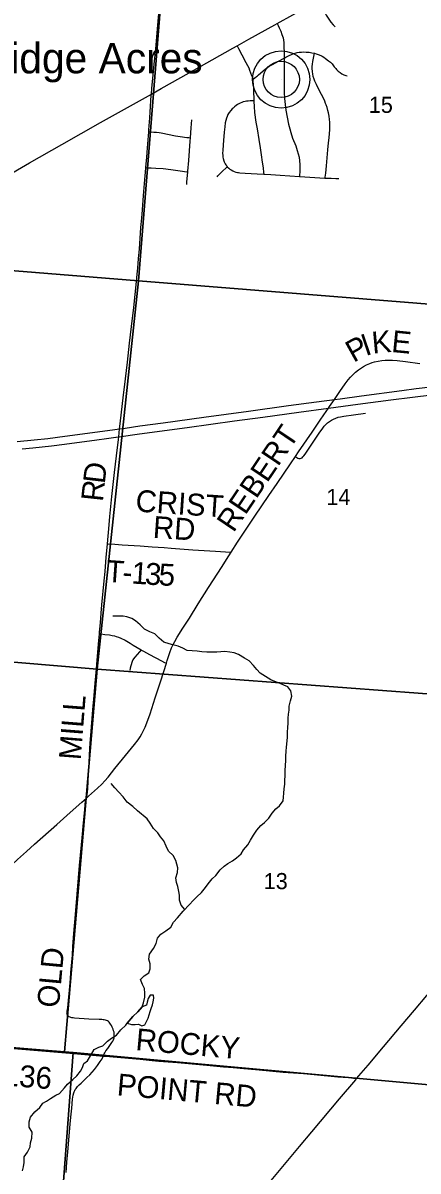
# Model space of a CAD drawing. Extents: x 0 to 1134, y 0 to 440.
# Drawn here: x 843.365 to 844.389, y 358.883 to 361.864 of the extents above; entities that cross this region are included whole.
import ezdxf

# ---------------------------------------------------------------- set-up
doc = ezdxf.new("R2010")
doc.units = 0
for name, color, linetype in [('GM_X_County_Road', 7, 'Continuous'), ('GM_X_County_Road_Text', 7, 'Continuous'), ('GM_X_Interstate_Route', 7, 'Continuous'), ('GM_X_Minor_Lake', 7, 'Continuous'), ('GM_X_Minor_River', 7, 'Continuous'), ('GM_X_Section', 7, 'Continuous'), ('GM_X_Section_Text', 7, 'Continuous'), ('GM_X_Township_Road', 7, 'Continuous'), ('GM_X_Township_Road_Text', 7, 'Continuous'), ('GM_X_Unincorporated', 7, 'Continuous'), ('GM_X_Unincorporated_Location', 7, 'Continuous'), ('GM_X_Unincorporated_Text', 7, 'Continuous')]:
    doc.layers.add(name, color=color, linetype=linetype)

msp = doc.modelspace()

# ---------------------------------------------------------------- linework, layer by layer
at = {"layer": 'GM_X_County_Road'}
for points in [[(844.0237, 361.8623), (844.0644, 361.8851), (844.1315, 361.9219)], [(843.92, 361.8044), (843.9506, 361.8216), (844.0174, 361.8588), (844.0237, 361.8623)], [(843.6977, 361.6793), (843.7229, 361.6933), (843.7743, 361.7225), (843.8556, 361.7681), (843.9091, 361.7983), (843.92, 361.8044)], [(843.3125, 361.4605), (843.3147, 361.4618), (843.382, 361.5007), (843.4655, 361.5487), (843.5657, 361.6051), (843.6822, 361.6707), (843.6977, 361.6793)], [(844.1449, 360.8463), (844.1568, 360.8637), (844.1598, 360.8682), (844.1722, 360.8863), (844.1861, 360.9066), (844.2003, 360.9271), (844.2079, 360.937), (844.214, 360.9441), (844.2205, 360.9508), (844.2273, 360.9572), (844.2345, 360.9633), (844.2396, 360.967), (844.2475, 360.972), (844.2558, 360.9763), (844.2644, 360.9801), (844.2703, 360.9822), (844.2763, 360.984), (844.2855, 360.9861), (844.2948, 360.9875), (844.3041, 360.9884), (844.3135, 360.9887), (844.3229, 360.9885), (844.3353, 360.9875), (844.3569, 360.9849), (844.3939, 360.98)], [(844.0711, 360.738), (844.0793, 360.75), (844.1144, 360.8013), (844.1353, 360.8322), (844.1449, 360.8463)], [(843.9046, 360.4899), (843.9212, 360.5156), (843.9366, 360.5389), (843.9519, 360.5623), (843.9657, 360.583), (844.0023, 360.6371), (844.0234, 360.6678), (844.0583, 360.7193), (844.0711, 360.738)], [(843.7366, 360.2016), (843.739, 360.209), (843.7458, 360.2297), (843.7501, 360.2414), (843.7539, 360.25), (843.7582, 360.2583), (843.7645, 360.2691), (843.7794, 360.2927), (843.7962, 360.3189), (843.8194, 360.3556), (843.8459, 360.3977), (843.8808, 360.4529), (843.8925, 360.4712), (843.9046, 360.4899)], [(843.5293, 359.851), (843.5347, 359.8559), (843.5578, 359.8767), (843.5689, 359.8875), (843.5773, 359.8965), (843.5853, 359.906), (843.6028, 359.9278), (843.6302, 359.9616), (843.6536, 359.9906), (843.663, 360.0029), (843.6683, 360.0106), (843.6731, 360.0185), (843.6774, 360.0267), (843.6813, 360.0351), (843.6859, 360.0466), (843.6941, 360.07), (843.7078, 360.1113), (843.7221, 360.1557), (843.7366, 360.2016)], [(842.9578, 359.3329), (842.9846, 359.3579), (843.0635, 359.4322), (843.0791, 359.4466), (843.1019, 359.4677), (843.1202, 359.4844), (843.1522, 359.5137), (843.1924, 359.5504), (843.2304, 359.5845), (843.2628, 359.6135), (843.2953, 359.6422), (843.3371, 359.6793), (843.3508, 359.6919), (843.3739, 359.7127), (843.3946, 359.7314), (843.4526, 359.783), (843.4874, 359.814), (843.5177, 359.8407), (843.5293, 359.851)], [(844.2299, 359.1229), (844.2596, 359.1582), (844.2997, 359.2057), (844.3457, 359.2604), (844.38, 359.3006), (844.4121, 359.3385), (844.4403, 359.3717), (844.4786, 359.4166), (844.4989, 359.4401), (844.5095, 359.4515), (844.5152, 359.4571)], [(843.9834, 358.8296), (844.0036, 358.8536), (844.0814, 358.9466), (844.1134, 358.9847), (844.1856, 359.0702), (844.2276, 359.1201), (844.2299, 359.1229)]]:
    msp.add_lwpolyline(points, dxfattribs=at)
at = {"layer": 'GM_X_Interstate_Route'}
msp.add_line((843.6051, 360.7882), (843.6061, 360.7883), dxfattribs=at)
for points in [[(843.6154, 360.8103), (843.6301, 360.8122), (843.6674, 360.8175), (843.7284, 360.8256), (843.8336, 360.84), (843.9498, 360.8562), (844.0536, 360.8703), (844.1259, 360.8802), (844.1722, 360.8863), (844.1871, 360.8883), (844.2427, 360.896), (844.3472, 360.91), (844.3842, 360.9147), (844.4521, 360.9222), (844.5148, 360.9288), (844.5746, 360.9344), (844.579, 360.9348)], [(843.6061, 360.7883), (843.6129, 360.7892), (843.6665, 360.7967), (843.7907, 360.8137), (843.9136, 360.8308), (843.9868, 360.8406), (844.0797, 360.8534), (844.1568, 360.8637), (844.2327, 360.8739), (844.3189, 360.8854), (844.3744, 360.8927), (844.4237, 360.8985), (844.4762, 360.9042), (844.5541, 360.912), (844.5818, 360.9144)], [(843.3493, 360.7773), (843.3937, 360.7815), (843.4294, 360.7851), (843.473, 360.7907), (843.5965, 360.8077), (843.6154, 360.8103)], [(843.3627, 360.7579), (843.3905, 360.7607), (843.4391, 360.7659), (843.4722, 360.7699), (843.5174, 360.7761), (843.5506, 360.7807), (843.5877, 360.7857), (843.6051, 360.7882)]]:
    msp.add_lwpolyline(points, dxfattribs=at)
at = {"layer": 'GM_X_Minor_Lake'}
for points in [[(843.635, 359.2669), (843.6463, 359.2634), (843.6553, 359.2637), (843.664, 359.2643), (843.6727, 359.2604), (843.6803, 359.2626), (843.6849, 359.2713), (843.6892, 359.2796), (843.6916, 359.2886), (843.6943, 359.2969), (843.6974, 359.3052), (843.7006, 359.3143), (843.7026, 359.3222), (843.7042, 359.3317), (843.7035, 359.3396), (843.6948, 359.3397), (843.6894, 359.3307), (843.687, 359.3217), (843.6854, 359.3141), (843.6737, 359.3097)], [(843.6737, 359.3097), (843.6629, 359.2962), (843.6495, 359.2842), (843.635, 359.2669)]]:
    msp.add_lwpolyline(points, dxfattribs=at)
at = {"layer": 'GM_X_Minor_River'}
for points in [[(843.7906, 360.2342), (843.7793, 360.2408), (843.7668, 360.2458), (843.7536, 360.2494), (843.7437, 360.2522), (843.7301, 360.2561), (843.7181, 360.2665), (843.7065, 360.2781), (843.6936, 360.2832), (843.6796, 360.2898), (843.6684, 360.3013), (843.6563, 360.3113), (843.6466, 360.3179), (843.6337, 360.3218), (843.6242, 360.3235), (843.6105, 360.3236), (843.5976, 360.3238)], [(843.7803, 359.5574), (843.7967, 359.5751), (843.8058, 359.5856), (843.8154, 359.5946), (843.8276, 359.6059), (843.8382, 359.6191), (843.8447, 359.6289), (843.8554, 359.6421), (843.865, 359.6504), (843.8757, 359.6647), (843.8867, 359.6749), (843.8962, 359.6813), (843.9084, 359.6887), (843.9183, 359.6959), (843.9304, 359.7064), (843.9362, 359.7174), (843.9476, 359.7298), (843.9545, 359.7419), (843.9626, 359.7555), (843.971, 359.7683), (843.9817, 359.78), (843.9912, 359.7882), (844.0019, 359.7988), (844.0111, 359.8123), (844.0202, 359.8233), (844.0297, 359.8315), (844.0393, 359.844), (844.0405, 359.8538), (844.0409, 359.8641), (844.0422, 359.8754), (844.0438, 359.8872), (844.0439, 359.8985), (844.0443, 359.9084), (844.0444, 359.9228), (844.0453, 359.9361), (844.0461, 359.949), (844.0462, 359.9603), (844.0471, 359.9728), (844.0479, 359.9834), (844.0499, 359.9997), (844.0507, 360.0096), (844.0508, 360.0236), (844.0517, 360.0335), (844.0525, 360.0471), (844.0526, 360.0585), (844.0535, 360.0691), (844.0547, 360.0793), (844.0551, 360.0903), (844.0582, 360.1035), (844.0621, 360.1164), (844.0596, 360.1301), (844.0513, 360.14), (844.0415, 360.1446), (844.0313, 360.1485), (844.0178, 360.1539), (844.0076, 360.1585), (843.9933, 360.167), (843.9797, 360.1758), (843.9711, 360.1853), (843.9621, 360.1956), (843.9512, 360.2075), (843.9388, 360.2144), (843.9237, 360.224), (843.912, 360.2282), (843.9007, 360.2306), (843.8878, 360.2318), (843.878, 360.2311), (843.8674, 360.2301), (843.8549, 360.2298), (843.8413, 360.2299), (843.8284, 360.2315), (843.8164, 360.2327), (843.7906, 360.2342)], [(843.7846, 359.5621), (843.7753, 359.573), (843.7709, 359.586), (843.7703, 359.5989), (843.7685, 359.6088), (843.766, 359.6221), (843.7631, 359.632), (843.7613, 359.6445), (843.7657, 359.6581), (843.7666, 359.6699), (843.764, 359.6798), (843.7611, 359.6893), (843.7541, 359.7019), (843.7417, 359.7135), (843.7357, 359.7265), (843.7298, 359.7406), (843.7216, 359.7509), (843.7141, 359.7613), (843.7033, 359.7724), (843.6943, 359.7858), (843.6865, 359.7973), (843.6617, 359.8184), (843.6493, 359.8292), (843.6346, 359.8408), (843.6245, 359.8546), (843.6133, 359.8665), (843.6028, 359.8776), (843.5938, 359.8891)], [(843.7221, 359.4978), (843.7351, 359.5067), (843.7484, 359.5164), (843.755, 359.5296), (843.7657, 359.5405), (843.7803, 359.5574)], [(843.3634, 358.8834), (843.3658, 358.8936), (843.3674, 358.9049), (843.368, 358.9201), (843.3768, 358.9317), (843.3838, 358.946), (843.3839, 358.9559), (843.3879, 358.9687), (843.3884, 358.9843), (843.381, 358.9972), (843.3808, 359.0105), (843.384, 359.023), (843.3951, 359.0365), (843.4081, 359.0481), (843.4158, 359.059), (843.4257, 359.0645), (843.4364, 359.0712), (843.4497, 359.0798), (843.4592, 359.0846), (843.4726, 359.0988), (843.4803, 359.1089), (843.4941, 359.1209), (843.504, 359.1306), (843.5136, 359.1423), (843.5194, 359.152), (843.5225, 359.1619), (843.5321, 359.1693), (843.5398, 359.1825), (843.5495, 359.1983), (843.5616, 359.2046), (843.5715, 359.2082), (843.5837, 359.2202), (843.594, 359.2277), (843.607, 359.2359), (843.6185, 359.2494), (843.6311, 359.2617), (843.635, 359.2669), (843.6495, 359.2842), (843.6629, 359.2962), (843.6737, 359.3097), (843.6772, 359.3199), (843.6804, 359.3346), (843.6809, 359.3445), (843.6795, 359.3566), (843.6744, 359.3677), (843.6693, 359.3806), (843.6792, 359.3896), (843.6914, 359.3978), (843.6945, 359.408), (843.6943, 359.4212), (843.6911, 359.4334), (843.6927, 359.4459), (843.7031, 359.4605), (843.7097, 359.4737), (843.7137, 359.4873), (843.7221, 359.4978)]]:
    msp.add_lwpolyline(points, dxfattribs=at)
at = {"layer": 'GM_X_Section'}
for points in [[(842.7231, 362.2874), (843.7455, 362.2116), (843.6646, 361.1946), (842.6377, 361.2776)], [(843.7455, 362.2116), (844.7599, 362.131), (844.6664, 361.1141), (843.6646, 361.1946)], [(842.6377, 361.2776), (843.6646, 361.1946), (843.5569, 360.1863), (842.5486, 360.2705)], [(843.6646, 361.1946), (844.6664, 361.1141), (844.5745, 360.1103), (843.5569, 360.1863)], [(842.5486, 360.2705), (843.5569, 360.1863), (843.4725, 359.1925), (842.4696, 359.2746), (842.4578, 359.2752)], [(843.5569, 360.1863), (844.5745, 360.1103), (844.4842, 359.101), (843.4949, 359.1906), (843.4725, 359.1925)], [(842.4696, 359.2746), (843.4725, 359.1925), (843.4949, 359.1906), (843.4223, 358.2223), (842.4019, 358.3021)], [(843.4949, 359.1906), (844.4842, 359.101), (844.5175, 359.0975), (844.4326, 358.1255), (843.4223, 358.2223)]]:
    msp.add_lwpolyline(points, close=True, dxfattribs=at)
at = {"layer": 'GM_X_Township_Road'}
for points in [[(844.1315, 361.9219), (844.1332, 361.9184), (844.1382, 361.9081), (844.1437, 361.8977), (844.1512, 361.8839), (844.1561, 361.876), (844.1633, 361.8659), (844.1691, 361.8586), (844.1739, 361.8534)], [(843.6977, 361.6793), (843.6991, 361.6947), (843.7015, 361.7194), (843.7051, 361.7565), (843.7091, 361.7966), (843.7145, 361.8585), (843.7175, 361.8984)], [(844.0237, 361.8623), (844.0264, 361.857), (844.0292, 361.8515), (844.033, 361.843), (844.0363, 361.8343), (844.039, 361.8255), (844.0403, 361.8196), (844.0411, 361.8135), (844.0415, 361.8073), (844.0421, 361.7824), (844.0423, 361.7729)], [(843.92, 361.8044), (843.9238, 361.7972), (843.9326, 361.7807), (843.9429, 361.7616), (843.9471, 361.7532), (843.95, 361.7471), (843.9525, 361.7409), (843.955, 361.7343), (843.9576, 361.7277), (843.959, 361.7236), (843.9599, 361.7195), (843.9603, 361.7177)], [(844.0423, 361.7729), (844.0465, 361.7753), (844.0548, 361.7795), (844.0609, 361.7823), (844.0662, 361.7843), (844.0704, 361.7857), (844.0758, 361.787), (844.0811, 361.7877), (844.0865, 361.7882), (844.0921, 361.7885), (844.0993, 361.7884), (844.107, 361.7879), (844.1136, 361.7867), (844.1194, 361.7855), (844.1207, 361.7851)], [(843.9603, 361.7177), (843.9622, 361.719), (843.9661, 361.7215), (843.9705, 361.7248), (843.9729, 361.727), (843.9752, 361.7289), (843.9802, 361.7333), (843.9872, 361.7395), (843.9923, 361.7436), (843.9972, 361.7473), (844.0035, 361.7516), (844.0113, 361.7561), (844.0276, 361.7648), (844.0423, 361.7729)], [(844.0423, 361.7729), (844.0421, 361.7142), (844.042, 361.7017), (844.0423, 361.6831), (844.0431, 361.6677), (844.0447, 361.6525), (844.0466, 361.6373), (844.0497, 361.619), (844.0535, 361.6008), (844.0563, 361.5887), (844.059, 361.5798), (844.064, 361.5651), (844.0718, 361.5448), (844.0761, 361.5331), (844.0787, 361.5242), (844.0806, 361.5151), (844.0819, 361.5059), (844.0826, 361.4966), (844.0827, 361.4873), (844.0822, 361.478), (844.0817, 361.4681), (844.0815, 361.4654)], [(844.1475, 361.4613), (844.148, 361.4638), (844.149, 361.4688), (844.1498, 361.4735), (844.1514, 361.4929), (844.1553, 361.5349), (844.157, 361.553), (844.1583, 361.5652), (844.1595, 361.5773), (844.16, 361.5866), (844.1603, 361.5962), (844.1601, 361.6061), (844.1597, 361.6134), (844.1589, 361.622), (844.1573, 361.6302), (844.1556, 361.6362), (844.1533, 361.6443), (844.151, 361.6509), (844.1495, 361.6547), (844.1473, 361.6604), (844.143, 361.67), (844.1348, 361.686), (844.1256, 361.7044), (844.1218, 361.7129), (844.1197, 361.7181), (844.1176, 361.7247), (844.1159, 361.7319), (844.1152, 361.7371), (844.1148, 361.7463), (844.115, 361.7511), (844.1153, 361.757), (844.1162, 361.7638), (844.1178, 361.7726), (844.1198, 361.7811), (844.1207, 361.7851)], [(844.1207, 361.7851), (844.125, 361.7839), (844.1304, 361.7822), (844.1371, 361.7793), (844.1408, 361.7773), (844.1449, 361.7748), (844.1493, 361.7719), (844.1571, 361.7659), (844.1619, 361.7619), (844.1663, 361.7576), (844.1682, 361.7553), (844.1719, 361.7503), (844.1757, 361.7455), (844.1779, 361.7433), (844.1824, 361.7391), (844.1871, 361.7352), (844.1918, 361.7318), (844.1951, 361.7298), (844.197, 361.7289), (844.1997, 361.728), (844.2023, 361.7272), (844.205, 361.7265)], [(843.9603, 361.7177), (843.9608, 361.715), (843.9611, 361.7114), (843.9616, 361.7061), (843.9625, 361.6906), (843.9631, 361.6619)], [(843.691, 361.5816), (843.6913, 361.5863), (843.6937, 361.6172), (843.6974, 361.6761), (843.6977, 361.6793)], [(843.9631, 361.6619), (843.9602, 361.6617), (843.954, 361.6613), (843.9489, 361.661), (843.9447, 361.6606), (843.9408, 361.66), (843.9355, 361.6588), (843.932, 361.6575), (843.9277, 361.6557), (843.9244, 361.6539), (843.9212, 361.652), (843.9171, 361.6492), (843.9129, 361.646), (843.9096, 361.643), (843.9073, 361.6409), (843.9033, 361.6362), (843.8994, 361.6313), (843.8977, 361.6287), (843.8962, 361.626), (843.8939, 361.6214), (843.8921, 361.6169), (843.8904, 361.6107), (843.8891, 361.6043), (843.8877, 361.594), (843.8867, 361.5807), (843.8846, 361.559), (843.8837, 361.5478), (843.8827, 361.5327), (843.8824, 361.5256), (843.8826, 361.5201), (843.8831, 361.5156), (843.8838, 361.5119), (843.8854, 361.5063), (843.8866, 361.5034), (843.8894, 361.4978), (843.8911, 361.4952), (843.8929, 361.4926), (843.8946, 361.4903)], [(843.9631, 361.6619), (843.9631, 361.6596), (843.9639, 361.6472), (843.9654, 361.6312), (843.9687, 361.6067), (843.9718, 361.5887), (843.9762, 361.5611), (843.9798, 361.5397), (843.9826, 361.5213), (843.9853, 361.5028), (843.9873, 361.4875), (843.9888, 361.476), (843.9894, 361.4713)], [(843.7987, 361.5655), (843.801, 361.5914), (843.8027, 361.6122)], [(843.6835, 361.4882), (843.6858, 361.515), (843.6878, 361.5398), (843.691, 361.5816)], [(843.691, 361.5816), (843.6933, 361.5814), (843.7039, 361.5806), (843.7111, 361.58), (843.7179, 361.5792), (843.7232, 361.5783), (843.7602, 361.5707), (843.7727, 361.5688), (843.79, 361.5666), (843.7945, 361.5661), (843.7987, 361.5655)], [(843.7919, 361.477), (843.792, 361.4789), (843.7945, 361.507), (843.7962, 361.532), (843.798, 361.5571), (843.7987, 361.5655)], [(843.868, 361.4643), (843.8704, 361.4672), (843.8746, 361.4716), (843.8793, 361.4761), (843.8946, 361.4903)], [(843.8946, 361.4903), (843.8984, 361.4871), (843.9015, 361.4847), (843.9047, 361.4826), (843.9091, 361.4801), (843.9126, 361.4784), (843.9167, 361.4769), (843.9206, 361.4759), (843.9233, 361.4754), (843.9273, 361.4751), (843.9405, 361.4742), (843.9716, 361.4725), (843.9894, 361.4713)], [(843.5839, 360.5116), (843.5882, 360.5604), (843.5901, 360.5821), (843.5955, 360.6346), (843.5988, 360.6655), (843.6022, 360.6964), (843.6073, 360.7396), (843.6121, 360.7828), (843.6129, 360.7892), (843.6154, 360.8103), (843.6169, 360.8229), (843.6204, 360.8537), (843.6247, 360.8908), (843.6304, 360.9401), (843.6355, 360.9833), (843.6411, 361.0327), (843.6461, 361.0759), (843.652, 361.1253), (843.6558, 361.1592), (843.6585, 361.1839), (843.6611, 361.2117), (843.6625, 361.2272), (843.6646, 361.2519), (843.6666, 361.2767), (843.6707, 361.3324), (843.6727, 361.3572), (843.6744, 361.3789), (843.6775, 361.416), (843.6799, 361.447), (843.6834, 361.4872), (843.6835, 361.4882)], [(843.6835, 361.4882), (843.6864, 361.4881), (843.6969, 361.488), (843.7094, 361.4873), (843.7285, 361.4857), (843.7484, 361.4831), (843.7724, 361.4796), (843.7897, 361.4773), (843.7919, 361.477)], [(843.7896, 361.4445), (843.7899, 361.4508), (843.7919, 361.477)], [(843.9894, 361.4713), (844.0071, 361.4701), (844.0319, 361.4685), (844.0815, 361.4654)], [(844.0815, 361.4654), (844.0955, 361.4645), (844.1475, 361.4613)], [(844.1475, 361.4613), (844.1525, 361.461), (844.1635, 361.4606), (844.1757, 361.4602), (844.1841, 361.4602)], [(844.0711, 360.738), (844.0724, 360.737), (844.0749, 360.7353), (844.0775, 360.7337), (844.08, 360.7329), (844.0831, 360.7327), (844.0861, 360.7335), (844.0886, 360.7351), (844.0908, 360.7373), (844.0928, 360.7397), (844.0964, 360.7447), (844.1034, 360.755), (844.1103, 360.7655), (844.1329, 360.7991), (844.1419, 360.8118), (844.1457, 360.8167), (844.15, 360.8212), (844.1546, 360.8254), (844.1595, 360.8293), (844.1647, 360.8326), (844.1702, 360.8355), (844.1759, 360.838), (844.1818, 360.84), (844.1879, 360.8415), (844.197, 360.8432), (844.2217, 360.8466), (844.2526, 360.8508)], [(843.5628, 360.2778), (843.5631, 360.282), (843.5654, 360.3068), (843.5676, 360.3315), (843.5696, 360.3532), (843.5753, 360.415), (843.5775, 360.4397), (843.5808, 360.4769), (843.5839, 360.5109), (843.5839, 360.5116)], [(843.5839, 360.5116), (843.5854, 360.5115), (843.6033, 360.5106), (843.6219, 360.5093), (843.6375, 360.5082), (843.653, 360.5072), (843.6685, 360.5062), (843.6996, 360.5039), (843.7306, 360.5017), (843.7493, 360.5003), (843.8051, 360.4963), (843.8642, 360.4926), (843.9027, 360.4901), (843.9046, 360.4899)], [(843.5293, 359.851), (843.5296, 359.8522), (843.5301, 359.8552), (843.5308, 359.8595), (843.5325, 359.8757), (843.5337, 359.8946), (843.535, 359.9138), (843.536, 359.9417), (843.5371, 359.9633), (843.539, 359.9942), (843.5419, 360.0253), (843.5461, 360.0809), (843.5494, 360.118), (843.5521, 360.1494), (843.5543, 360.1778), (843.5561, 360.1985), (843.5605, 360.2511), (843.5628, 360.2778)], [(843.5628, 360.2778), (843.5674, 360.2774), (843.5766, 360.2765), (843.5888, 360.2749), (843.596, 360.2736), (843.602, 360.2723), (843.6068, 360.2709), (843.6126, 360.2689), (843.6182, 360.2665), (843.6293, 360.2611), (843.6431, 360.2532), (843.6506, 360.2485), (843.6608, 360.2421), (843.6709, 360.2363)], [(843.6709, 360.2363), (843.6666, 360.2313), (843.6547, 360.2176), (843.6512, 360.2127), (843.6498, 360.2103), (843.6476, 360.2056), (843.6466, 360.2031), (843.6449, 360.1977), (843.6441, 360.1947), (843.6429, 360.1888), (843.6418, 360.183)], [(843.6709, 360.2363), (843.6741, 360.2344), (843.6773, 360.2326), (843.6931, 360.2242), (843.724, 360.2075), (843.732, 360.2037), (843.7355, 360.2021), (843.7366, 360.2016)], [(843.5728, 359.1814), (843.5738, 359.1839), (843.5753, 359.187), (843.5772, 359.1903), (843.58, 359.1948), (843.5844, 359.2012), (843.5883, 359.2067), (843.5951, 359.2164), (843.5974, 359.2203), (843.5992, 359.2236), (843.6002, 359.2262), (843.6009, 359.2287), (843.6014, 359.2316), (843.6015, 359.2351), (843.6015, 359.238), (843.6013, 359.2414), (843.6009, 359.2437), (843.5998, 359.2471), (843.5982, 359.2514), (843.596, 359.2566), (843.5941, 359.2608), (843.5919, 359.2646), (843.5901, 359.2673), (843.5881, 359.2695), (843.5861, 359.2713), (843.5835, 359.2729), (843.581, 359.2739), (843.5784, 359.2747), (843.5755, 359.2753), (843.5726, 359.2757), (843.5694, 359.2761), (843.5622, 359.2765), (843.5354, 359.2776), (843.4981, 359.2802), (843.4948, 359.2805), (843.4914, 359.2811), (843.4889, 359.2818), (843.487, 359.2825), (843.4849, 359.2836), (843.4834, 359.2846), (843.4821, 359.2858), (843.4808, 359.2872), (843.4801, 359.2883), (843.4794, 359.2897), (843.479, 359.2911), (843.4788, 359.2929), (843.479, 359.2947), (843.4796, 359.298), (843.4805, 359.3027), (843.4812, 359.3073), (843.4823, 359.3163), (843.4831, 359.3258), (843.4853, 359.3529), (843.4878, 359.3819), (843.4892, 359.3985), (843.4913, 359.4253), (843.4929, 359.4438), (843.4943, 359.4657), (843.4969, 359.4997), (843.5011, 359.5491), (843.5054, 359.6017), (843.5116, 359.6759), (843.5139, 359.703), (843.5182, 359.7484), (843.5217, 359.787), (843.525, 359.8214), (843.526, 359.8338), (843.5272, 359.8431), (843.5279, 359.8462), (843.5293, 359.851)], [(843.1073, 359.2217), (843.1739, 359.2158), (843.2045, 359.2132), (843.2166, 359.2122), (843.2651, 359.2079), (843.3514, 359.2007), (843.4864, 359.1889), (843.5544, 359.1828), (843.5728, 359.1814)], [(843.4764, 358.879), (843.4773, 358.8912), (843.4786, 358.9069), (843.4808, 358.9322), (843.4848, 358.9742), (843.4875, 359.0046), (843.4888, 359.0225), (843.491, 359.0459), (843.4933, 359.0692), (843.4951, 359.0798), (843.4967, 359.0859), (843.4977, 359.0889), (843.499, 359.0918), (843.5004, 359.0944), (843.5025, 359.0976), (843.5065, 359.1023), (843.5102, 359.1067), (843.5152, 359.1114), (843.5232, 359.1187), (843.5307, 359.1256), (843.5381, 359.1329), (843.5442, 359.1397), (843.5504, 359.147), (843.558, 359.1571), (843.5653, 359.1673), (843.5698, 359.1743), (843.5717, 359.1788), (843.5728, 359.1814)], [(843.5728, 359.1814), (843.5791, 359.1809), (843.6686, 359.1732), (843.6995, 359.1702), (843.7174, 359.1687), (843.7656, 359.1645), (843.8416, 359.1577), (843.8847, 359.1538), (843.9095, 359.1516), (843.9373, 359.149), (843.9775, 359.1454), (844.0394, 359.1401), (844.092, 359.1359), (844.1287, 359.1326), (844.1811, 359.1279), (844.2089, 359.1255), (844.2168, 359.1248), (844.2267, 359.1233), (844.2299, 359.1229)]]:
    msp.add_lwpolyline(points, dxfattribs=at)
at = {"layer": 'GM_X_Unincorporated'}
for radius in [0.0744, 0.0472]:
    msp.add_circle((844.0343, 361.7173), radius, dxfattribs=at)
at = {"layer": 'GM_X_Unincorporated_Location'}
msp.add_line((844.0343, 361.7173), (844.0343, 361.7173), dxfattribs=at)

# ---------------------------------------------------------------- texts
at = {"layer": 'GM_X_County_Road_Text'}
for s, height, rotation, p in [('P', 0.0568, 29.137, (844.2218, 360.981)), ('I', 0.0568, 18.4498, (844.2528, 360.9985)), ('K', 0.0568, 5.1962, (844.2715, 361.0052)), ('E', 0.0568, 354.3619, (844.3185, 361.0098)), ('REBERT', 0.05682, 56.0638, (843.9107, 360.5387))]:
    msp.add_text(s, height=height, rotation=rotation, dxfattribs=at).set_placement(p)
at = {"layer": 'GM_X_Section_Text'}
for s, p in [('15', (844.2615, 361.6304)), ('14', (844.1515, 360.6123)), ('13', (843.989, 359.6149))]:
    msp.add_text(s, height=0.04186, rotation=0, dxfattribs=at).set_placement(p)
at = {"layer": 'GM_X_Township_Road_Text'}
for s, height, rotation, p in [('D', 0.0568, 83.304, (843.5767, 360.6659)), ('R', 0.0568, 83.9783, (843.5718, 360.6196)), ('CRIST', 0.05682, 356.1211, (843.6554, 360.5955)), ('RD', 0.05682, 356.0542, (843.7003, 360.5273)), ('T', 0.0568, 356.0564, (843.5789, 360.4131)), ('1', 0.0568, 356.1234, (843.6447, 360.4086)), ('3', 0.0568, 356.3167, (843.6798, 360.4062)), ('5', 0.0568, 357.1486, (843.7156, 360.4039)), ('-', 0.0568, 356.07, (843.6213, 360.4102)), ('MILL', 0.05682, 85.5152, (843.5143, 359.9489)), ('OLD', 0.05682, 84.7464, (843.4576, 359.3054)), ('ROCKY', 0.05682, 354.9449, (843.6553, 359.1971)), ('T-136', 0.05682, 355.2365, (843.2396, 359.1116)), ('POINT RD', 0.05682, 354.9167, (843.6068, 359.0798))]:
    msp.add_text(s, height=height, rotation=rotation, dxfattribs=at).set_placement(p)
at = {"layer": 'GM_X_Unincorporated_Text'}
msp.add_text('Park Ridge Acres', height=0.078977, rotation=0, dxfattribs=at).set_placement((843.009, 361.7331))

doc.saveas('drawing.dxf')
